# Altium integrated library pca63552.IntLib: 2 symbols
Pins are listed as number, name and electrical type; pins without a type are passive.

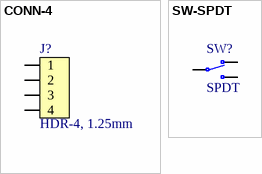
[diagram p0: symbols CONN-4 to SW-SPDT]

## CONN-4
designator J?, comment HDR-4, 1.25mm
Connector Header Through Hole 4 position 0.049" (1.25mm); Part Number: 1734598-4; Manufacturer: TE Connectivity; Artikkelnr Noca: N.A.
footprint 1734598-4
pins: 1, 2, 3, 4

## SW-SPDT
designator SW?, comment SPDT
SWITCH SNAP ACTION SPDT 1A 125V; Part Number: D2F-F; Manufacturer: Omron; Artikkelnr Noca: N.A.
footprint D2F-F
pins: 1 N.C, 2 COM, 3 N.O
